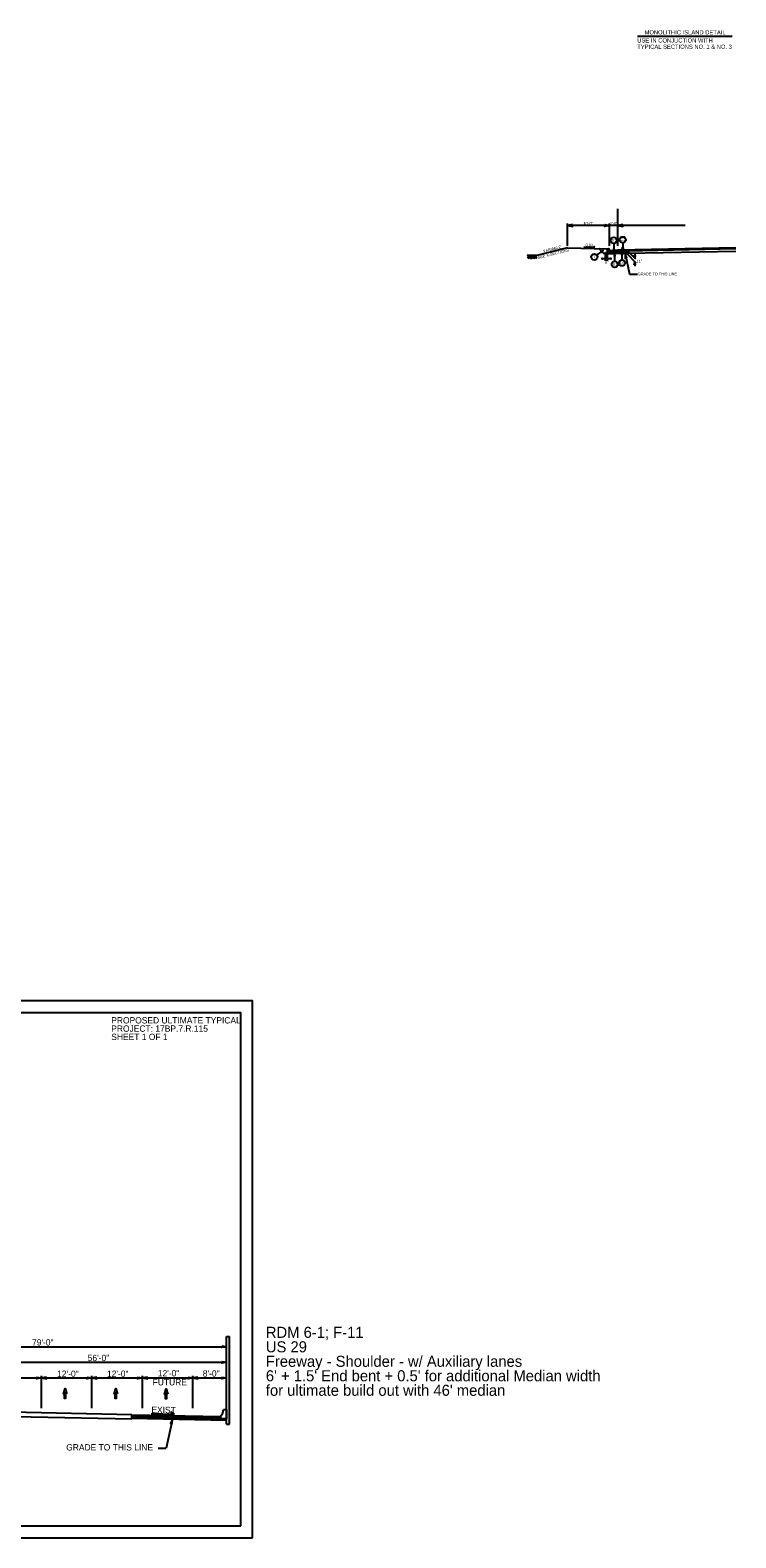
# Model space of a CAD drawing. Extents: x 1901582 to 1902252, y 193723 to 194156.
# Drawn here: x 1901790 to 1901957.6, y 193784.8 to 194142.7 of the extents above; entities that cross this region are included whole.
import ezdxf

# ---------------------------------------------------------------- set-up
doc = ezdxf.new("R2010")
doc.units = 0
for name, color, linetype in [('Default', 7, 'Continuous'), ('Old_Level_1', 7, 'Continuous'), ('Old_Level_11', 7, 'Continuous'), ('Old_Level_2', 7, 'Continuous'), ('Old_Level_20', 7, 'Continuous'), ('Prop Dimension', 7, 'Continuous'), ('Prop Dimension Text', 7, 'Continuous'), ('Prop Roadway Bridge', 7, 'Continuous'), ('Scratch_Level_0', 7, 'Continuous'), ('Scratch_Level_3', 7, 'Continuous'), ('Typical Bridge Rail CELL', 7, 'Continuous'), ('Typical Curb CELL', 7, 'Continuous'), ('Typical Pavement Slope Information CELL', 7, 'Continuous'), ('Typical Terminator CELL', 7, 'Continuous')]:
    doc.layers.add(name, color=color, linetype=linetype)

# ---------------------------------------------------------------- blocks, each defined once
blk = doc.blocks.new('TERMINATOR')
at = {"layer": 'Typical Terminator CELL'}
blk.add_lwpolyline([(-0.47, 0.08), (0, 0), (-0.47, -0.08), (-0.41, 0)], close=True, dxfattribs=at)

msp = doc.modelspace()

# ---------------------------------------------------------------- linework, layer by layer
at = {"layer": 'Default'}
for p, q in [((1901929.6, 194096.38), (1901927.6, 194096.38)), ((1901925.62, 194088.5), (1901926.62, 194088.5)), ((1901926.62, 194088), (1901926.62, 194089.47)), ((1901927.12, 194088), (1901927.12, 194089.47)), ((1901927.12, 194088.5), (1901928.12, 194088.5))]:
    msp.add_line(p, q, dxfattribs=at)
at = {"layer": 'Old_Level_1'}
for p, q in [((1901929.61, 194091.52), (1901929.61, 194100.3)), ((1901917.6, 194091.55), (1901917.6, 194096.88)), ((1901927.6, 194096.38), (1901917.6, 194096.38)), ((1901927.6, 194091.52), (1901927.6, 194096.88)), ((1901945.61, 194096.38), (1901929.61, 194096.38)), ((1901917.6, 194091.05), (1901910.3, 194089.22)), ((1901917.6, 194091.05), (1901927.1, 194090.86)), ((1901921.51, 194091.32), (1901924.1, 194091.22)), ((1901924.1, 194091.22), (1901923.77, 194091.39)), ((1901957.61, 194091.05), (1901929.61, 194090.49)), ((1901926.37, 194089.59), (1901925.06, 194090.9)), ((1901926.62, 194089.85), (1901926.37, 194089.59)), ((1901931.71, 194089.7), (1901926.37, 194089.59)), ((1901931.71, 194089.95), (1901926.62, 194089.85)), ((1901931.71, 194090.28), (1901929.61, 194090.24)), ((1901931.3, 194089.69), (1901932.32, 194084.84)), ((1901957.61, 194090.8), (1901931.71, 194090.28)), ((1901931.71, 194090.53), (1901933.76, 194088.42)), ((1901931.71, 194089.7), (1901931.71, 194090.28)), ((1901957.61, 194090.22), (1901931.71, 194089.7)), ((1901931.71, 194089.7), (1901933.82, 194087.52)), ((1901933.6, 194089.58), (1901933.6, 194088.58)), ((1901933.6, 194087.75), (1901933.6, 194086.75)), ((1901932.32, 194084.84), (1901934.23, 194084.84)), ((1901814.15, 193814.02), (1901778.15, 193814.74)), ((1901814.14, 193812.94), (1901814.15, 193814.02)), ((1901814.15, 193814.02), (1901835.15, 193813.6)), ((1901814.15, 193814.02), (1901814.15, 193813.18)), ((1901823.78, 193812.99), (1901822.32, 193806.04)), ((1901820.41, 193806.04), (1901822.32, 193806.04))]:
    msp.add_line(p, q, dxfattribs=at)
for points in [[(1901910.3, 194089.22), (1901908.06, 194089.22)], [(1901814.14, 193812.94), (1901778.15, 193813.66)]]:
    msp.add_lwpolyline(points, dxfattribs=at)
msp.add_lwpolyline([(1901839.99, 193787.6), (1901839.99, 193909.47), (1901680.62, 193909.47), (1901680.62, 193787.6)], close=True, dxfattribs=at)
at = {"layer": 'Old_Level_11'}
for p, q in [((1901934.27, 194141.31), (1901956.7, 194141.31)), ((1901928.61, 194092.12), (1901928.61, 194090.25)), ((1901930.73, 194092.25), (1901930.73, 194090.38)), ((1901908.1, 194089.22), (1901908.06, 194089.18)), ((1901908.83, 194088.44), (1901908.1, 194089.22)), ((1901908.52, 194088.42), (1901908.11, 194088.85)), ((1901908.36, 194089.22), (1901908.23, 194089.08)), ((1901908.76, 194089.22), (1901908.43, 194088.86)), ((1901909.16, 194089.22), (1901908.63, 194088.65)), ((1901909.55, 194089.21), (1901908.83, 194088.44)), ((1901908.95, 194088.42), (1901908.88, 194088.49)), ((1901909.27, 194088.42), (1901909.04, 194088.66)), ((1901909.61, 194088.42), (1901909.21, 194088.85)), ((1901909.92, 194088.42), (1901909.37, 194089.01)), ((1901910.3, 194088.42), (1901909.55, 194089.21)), ((1901909.92, 194089.22), (1901909.73, 194089.02)), ((1901910.3, 194089.22), (1901909.92, 194088.82)), ((1901910.3, 194088.86), (1901910.09, 194088.64)), ((1901924.59, 194089.32), (1901926.1, 194090.42)), ((1901928.84, 194087.86), (1901928.84, 194089.74)), ((1901930.6, 194088.22), (1901930.6, 194090.09))]:
    msp.add_line(p, q, dxfattribs=at)
for points in [[(1901930.85, 194091.05), (1901930.73, 194090.38), (1901930.62, 194091.05), (1901930.73, 194090.97)], [(1901925.49, 194090.12), (1901926.1, 194090.42), (1901925.63, 194089.93), (1901925.63, 194090.07)], [(1901928.49, 194090.92), (1901928.61, 194090.25), (1901928.73, 194090.92), (1901928.61, 194090.84)], [(1901928.95, 194089.07), (1901928.84, 194089.74), (1901928.72, 194089.06), (1901928.84, 194089.15)], [(1901930.71, 194089.42), (1901930.6, 194090.09), (1901930.48, 194089.42), (1901930.6, 194089.5)]]:
    msp.add_lwpolyline(points, close=True, dxfattribs=at)
for centre in [(1901928.61, 194092.85), (1901930.73, 194092.98), (1901924, 194088.89), (1901928.84, 194087.14), (1901930.6, 194087.49)]:
    msp.add_circle(centre, 0.725, dxfattribs=at)
at = {"layer": 'Prop Dimension'}
for p, q in [((1901757.65, 193830.16), (1901836.65, 193830.16)), ((1901780.65, 193826.46), (1901836.65, 193826.46)), ((1901780.65, 193822.76), (1901792.65, 193822.76)), ((1901792.65, 193815.55), (1901792.65, 193823.26)), ((1901792.65, 193822.76), (1901804.65, 193822.76)), ((1901804.65, 193815.55), (1901804.65, 193823.26)), ((1901804.65, 193822.76), (1901816.65, 193822.76)), ((1901816.65, 193815.55), (1901816.65, 193823.26)), ((1901816.65, 193822.76), (1901828.65, 193822.76)), ((1901828.65, 193815.55), (1901828.65, 193823.26)), ((1901828.65, 193822.76), (1901836.65, 193822.76)), ((1901814.14, 193813.77), (1901835.15, 193813.35)), ((1901814.14, 193813.44), (1901835.15, 193813.01)), ((1901814.15, 193813.18), (1901836.65, 193812.73))]:
    msp.add_line(p, q, dxfattribs=at)
for points in [[(1901798.67, 193818.94), (1901798.4, 193819.19), (1901798.4, 193817.86), (1901798.15, 193817.86), (1901798.15, 193819.19), (1901797.88, 193818.94), (1901798.27, 193820.21)], [(1901798.67, 193818.94), (1901798.4, 193819.19), (1901798.4, 193817.86), (1901798.15, 193817.86), (1901798.15, 193819.19), (1901797.88, 193818.94), (1901798.27, 193820.21)], [(1901810.71, 193818.94), (1901810.44, 193819.19), (1901810.44, 193817.86), (1901810.19, 193817.86), (1901810.19, 193819.19), (1901809.92, 193818.94), (1901810.31, 193820.21)], [(1901810.71, 193818.94), (1901810.44, 193819.19), (1901810.44, 193817.86), (1901810.19, 193817.86), (1901810.19, 193819.19), (1901809.92, 193818.94), (1901810.31, 193820.21)], [(1901822.65, 193818.87), (1901822.38, 193819.12), (1901822.38, 193817.78), (1901822.13, 193817.78), (1901822.13, 193819.12), (1901821.86, 193818.87), (1901822.26, 193820.14)], [(1901822.65, 193818.87), (1901822.38, 193819.12), (1901822.38, 193817.78), (1901822.13, 193817.78), (1901822.13, 193819.12), (1901821.86, 193818.87), (1901822.26, 193820.14)]]:
    msp.add_lwpolyline(points, close=True, dxfattribs=at)
at = {"layer": 'Prop Roadway Bridge'}
for p, q in [((1901836.65, 193811.79), (1901836.65, 193832.57)), ((1901836.65, 193832.57), (1901837.29, 193832.57)), ((1901837.29, 193811.79), (1901837.29, 193832.57)), ((1901836.65, 193811.79), (1901837.29, 193811.79))]:
    msp.add_line(p, q, dxfattribs=at)
at = {"layer": 'Scratch_Level_0'}
msp.add_lwpolyline([(1901842.8, 193784.79), (1901842.8, 193912.29), (1901677.8, 193912.29), (1901677.8, 193784.79)], close=True, dxfattribs=at)
at = {"layer": 'Typical Bridge Rail CELL'}
for p, q in [((1901835.15, 193813.69), (1901835.66, 193814.25)), ((1901835.15, 193813.69), (1901835.15, 193813.03)), ((1901836.65, 193813.03), (1901835.15, 193813.04)), ((1901835.78, 193814.49), (1901835.94, 193815.26)), ((1901835.94, 193815.26), (1901836.62, 193815.26)), ((1901836.62, 193815.26), (1901836.65, 193815.23)), ((1901836.65, 193815.23), (1901836.65, 193813.03))]:
    msp.add_line(p, q, dxfattribs=at)
msp.add_arc((1901835.29, 193814.59), 0.5, 317.8699, 348.0042, dxfattribs=at)
at = {"layer": 'Typical Curb CELL'}
for p, q in [((1901927.12, 194089.86), (1901927.1, 194090.86)), ((1901927.1, 194090.86), (1901927.36, 194090.86)), ((1901927.12, 194089.86), (1901929.62, 194089.91)), ((1901927.15, 194090.48), (1901927.3, 194090.53)), ((1901927.28, 194090.44), (1901927.15, 194090.48)), ((1901927.28, 194090.16), (1901927.18, 194090.09)), ((1901927.18, 194090.09), (1901927.34, 194090.05)), ((1901927.3, 194090.53), (1901927.28, 194090.44)), ((1901927.34, 194090.05), (1901927.28, 194090.16)), ((1901927.61, 194090.62), (1901927.61, 194090.63)), ((1901929.61, 194090.49), (1901927.86, 194090.38)), ((1901928.02, 194090.24), (1901927.99, 194090.12)), ((1901927.99, 194090.12), (1901928.11, 194090.12)), ((1901928.11, 194090.12), (1901928.02, 194090.24)), ((1901928.53, 194090.19), (1901928.42, 194090.11)), ((1901928.42, 194090.11), (1901928.59, 194090.08)), ((1901928.59, 194090.08), (1901928.53, 194090.19)), ((1901929.27, 194090.26), (1901929.23, 194090.15)), ((1901929.23, 194090.15), (1901929.36, 194090.14)), ((1901929.36, 194090.14), (1901929.27, 194090.26)), ((1901929.62, 194089.91), (1901929.61, 194090.49))]:
    msp.add_line(p, q, dxfattribs=at)
for centre in [(1901927.12, 194090.75), (1901927.17, 194090.57), (1901927.26, 194089.91), (1901927.27, 194090.3), (1901927.33, 194090.79), (1901927.39, 194090.35), (1901927.44, 194089.95), (1901927.57, 194090.19), (1901927.61, 194089.89), (1901927.65, 194090.38), (1901927.67, 194090.33), (1901927.67, 194090.01), (1901927.7, 194090.16), (1901927.78, 194089.92), (1901927.85, 194090.25), (1901927.87, 194090.35), (1901927.99, 194089.95), (1901928.07, 194090.32), (1901928.15, 194089.89), (1901928.16, 194090.36), (1901928.2, 194090.12), (1901928.27, 194090.28), (1901928.29, 194090.08), (1901928.33, 194090.32), (1901928.35, 194090.22), (1901928.36, 194089.91), (1901928.51, 194089.93), (1901928.52, 194090.32), (1901928.64, 194090.37), (1901928.68, 194089.98), (1901928.82, 194090.21), (1901928.86, 194089.92), (1901928.9, 194090.41), (1901928.92, 194090.36), (1901928.92, 194090.03), (1901928.95, 194090.19), (1901929.03, 194089.95), (1901929.09, 194090.28), (1901929.12, 194090.38), (1901929.24, 194089.98), (1901929.27, 194090.44), (1901929.32, 194090.34), (1901929.4, 194089.91), (1901929.41, 194090.43), (1901929.45, 194090.15), (1901929.52, 194090.31), (1901929.54, 194090.1), (1901929.58, 194090.34), (1901929.6, 194090.25), (1901929.61, 194089.94)]:
    msp.add_circle(centre, 0.00802, dxfattribs=at)
for centre, start, end in [((1901927.37, 194090.62), 1.1458, 91.1458), ((1901927.85, 194090.62), 181.1458, 273.5302)]:
    msp.add_arc(centre, 0.24, start, end, dxfattribs=at)
at = {"layer": 'Typical Pavement Slope Information CELL'}
for q in [(1901818.69, 193814.21), (1901823.41, 193814.61)]:
    msp.add_line((1901824.25, 193814.1), q, dxfattribs=at)
at = {"layer": 'Typical Terminator CELL'}
for points in [[(1901918.77, 194096.58), (1901917.6, 194096.38), (1901918.78, 194096.17), (1901918.63, 194096.38)], [(1901926.43, 194096.58), (1901927.6, 194096.38), (1901926.42, 194096.17), (1901926.57, 194096.38)], [(1901930.78, 194096.58), (1901929.61, 194096.38), (1901930.79, 194096.17), (1901930.64, 194096.38)], [(1901931.73, 194088.62), (1901931.3, 194089.69), (1901931.34, 194088.53), (1901931.51, 194088.71)], [(1901835.48, 193830.36), (1901836.65, 193830.16), (1901835.47, 193829.95), (1901835.62, 193830.16)], [(1901835.48, 193826.66), (1901836.65, 193826.46), (1901835.47, 193826.25), (1901835.62, 193826.46)], [(1901791.48, 193822.96), (1901792.65, 193822.76), (1901791.47, 193822.55), (1901791.62, 193822.76)], [(1901793.82, 193822.96), (1901792.65, 193822.76), (1901793.83, 193822.55), (1901793.68, 193822.76)], [(1901803.48, 193822.96), (1901804.65, 193822.76), (1901803.47, 193822.55), (1901803.62, 193822.76)], [(1901805.82, 193822.96), (1901804.65, 193822.76), (1901805.83, 193822.55), (1901805.68, 193822.76)], [(1901815.48, 193822.96), (1901816.65, 193822.76), (1901815.47, 193822.55), (1901815.62, 193822.76)], [(1901817.82, 193822.96), (1901816.65, 193822.76), (1901817.83, 193822.55), (1901817.68, 193822.76)], [(1901827.48, 193822.96), (1901828.65, 193822.76), (1901827.47, 193822.55), (1901827.62, 193822.76)], [(1901829.82, 193822.96), (1901828.65, 193822.76), (1901829.83, 193822.55), (1901829.68, 193822.76)], [(1901835.48, 193822.96), (1901836.65, 193822.76), (1901835.47, 193822.55), (1901835.62, 193822.76)], [(1901823.74, 193811.84), (1901823.78, 193812.99), (1901823.34, 193811.91), (1901823.57, 193812.01)]]:
    msp.add_lwpolyline(points, close=True, dxfattribs=at)

# ---------------------------------------------------------------- block references
at = {"layer": 'Old_Level_1', "xscale": 1.5, "yscale": 1.5}
msp.add_blockref('TERMINATOR', (1901926.62, 194088.5), dxfattribs=at)
for p, rotation in [((1901927.12, 194088.5), 180), ((1901933.6, 194088.58), -90), ((1901933.6, 194087.75), 90)]:
    msp.add_blockref('TERMINATOR', p, dxfattribs=dict(at, rotation=rotation))

# ---------------------------------------------------------------- texts
at = {"layer": 'Old_Level_1'}
for s, height, p in [('10\'-0"', 0.656, (1901921.35, 194096.51)), ('2\'-0"', 0.656, (1901927.69, 194096.52)), ('GRADE TO THIS LINE', 0.656, (1901934.32, 194084.53)), ('PROPOSED ULTIMATE TYPICAL', 1.5, (1901809.24, 193906.91)), ('PROJECT: 17BP.7.R.115', 1.5, (1901809.24, 193904.94)), ('SHEET 1 OF 1', 1.5, (1901809.24, 193902.97)), ('79\'-0"', 1.5, (1901790.42, 193830.45)), ('56\'-0"', 1.5, (1901803.64, 193826.75)), ('12\'-0"', 1.5, (1901796.39, 193823)), ('12\'-0"', 1.5, (1901808.22, 193823)), ('12\'-0"', 1.5, (1901820.3, 193823.12)), ('8\'-0"', 1.5, (1901830.98, 193823.07)), ('GRADE TO THIS LINE', 1.5, (1901798.54, 193805.53))]:
    msp.add_text(s, height=height, dxfattribs=at).set_placement(p)
for s, p in [('VARIABLE', (1901911.89, 194089.93)), ('SEE X-SECTIONS', (1901910.66, 194088.43))]:
    msp.add_text(s, height=0.656, rotation=14.0362, dxfattribs=at).set_placement(p)
at = {"layer": 'Old_Level_11'}
for s, p in [('MONOLITHIC ISLAND DETAIL', (1901935.92, 194141.73)), ('TYPICAL SECTIONS NO. 1 & NO. 3', (1901934.19, 194138.31)), ('USE IN CONJUCTION WITH', (1901934.19, 194139.81))]:
    msp.add_text(s, height=1, dxfattribs=at).set_placement(p)
at = {"layer": 'Old_Level_2'}
for s, height, rotation, p in [('0.02', 0.656, 357.7461, (1901921.91, 194091.42)), ('EXIST', 1.5, 359.2015, (1901818.76, 193814.44))]:
    msp.add_text(s, height=height, rotation=rotation, dxfattribs=at).set_placement(p)
at = {"layer": 'Old_Level_20'}
for s, p in [('R1', (1901928.15, 194092.54)), ('C2', (1901930.23, 194092.67)), ('T', (1901923.77, 194088.54)), ('6"', (1901926.55, 194087.33)), ('E1', (1901928.4, 194086.83)), ('D1', (1901930.08, 194087.19)), ('11"', (1901934.01, 194087.57))]:
    msp.add_text(s, height=0.649, dxfattribs=at).set_placement(p)
at = {"layer": 'Prop Dimension Text'}
msp.add_text('FUTURE', height=1.5, dxfattribs=at).set_placement((1901819.07, 193820.98))
at = {"layer": 'Scratch_Level_3'}
for s, height, p in [('RDM 6-1; F-11', 2.6257, (1901845.96, 193832.27)), ('US 29', 2.626, (1901845.96, 193828.83)), ('Freeway - Shoulder - w/ Auxiliary lanes', 2.6257, (1901845.96, 193825.39)), ("6' + 1.5' End bent + 0.5' for additional Median width", 2.6257, (1901845.96, 193821.95)), ("for ultimate build out with 46' median", 2.6257, (1901845.96, 193818.51))]:
    msp.add_text(s, height=height, dxfattribs=at).set_placement(p)

doc.saveas('drawing.dxf')
